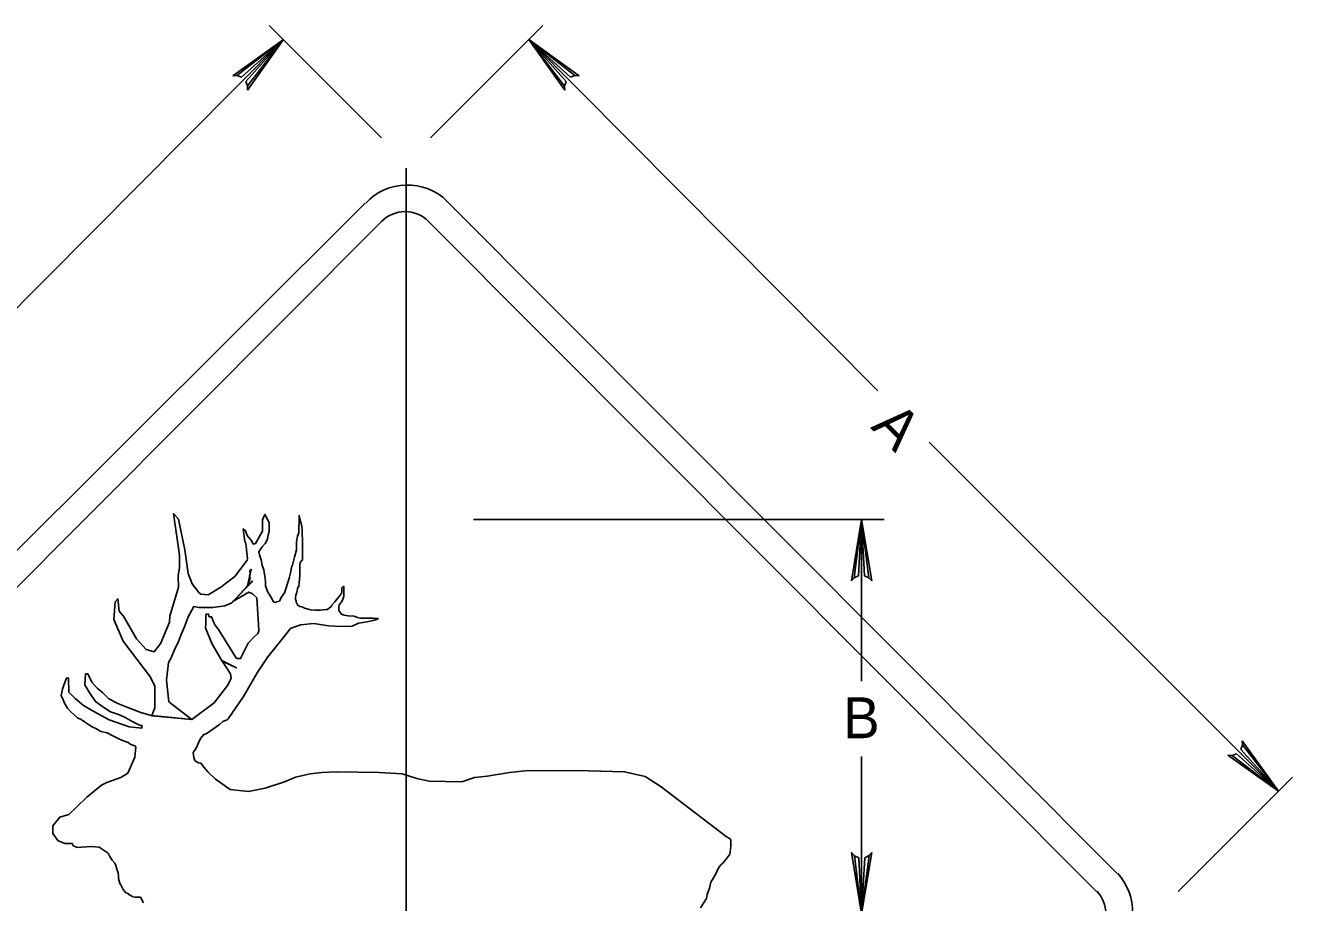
# Model space of a CAD drawing. Extents: x 0.013 to 0.196, y 0.005 to 0.259.
# Drawn here: x 0.0857 to 0.1633, y 0.1514 to 0.2051 of the extents above; entities that cross this region are included whole.
import ezdxf

# ---------------------------------------------------------------- set-up
doc = ezdxf.new("R2010")
doc.units = 0
doc.layers.add('11', color=7, linetype='Continuous')
doc.layers.add('3', color=7, linetype='Continuous')

# ---------------------------------------------------------------- blocks, each defined once
blk = doc.blocks.new('RARROW')
at = {"layer": '3'}
for p, q in [((-2.156, 0.28500000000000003), (-2.2665, 0.384625)), ((-2.2665, 0.384625), (0, 0)), ((0, 0), (-2.2665, -0.379125)), ((-2.156, 0.28500000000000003), (-2.075625, 0.12075)), ((0, 0), (-2.156, 0.28500000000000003)), ((-2.14975, -0.2705), (0, 0)), ((-2.075625, 0.12075), (0, 0)), ((0, 0), (-2.074, -0.108)), ((-2.2665, -0.379125), (-2.14975, -0.2705)), ((-2.074, -0.108), (-2.14975, -0.2705))]:
    blk.add_line(p, q, dxfattribs=at)

msp = doc.modelspace()

# ---------------------------------------------------------------- linework, layer by layer
at = {"layer": '11'}
for p, q in [((0.0655, 0.153375), (0.1065, 0.19425)), ((0.1115, 0.194375), (0.1525, 0.15325))]:
    msp.add_line(p, q, dxfattribs=at)
for centre, radius, start, end in [((0.10907575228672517, 0.19186675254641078), 0.003488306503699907, 45.97564444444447, 136.90506388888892), ((0.1499707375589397, 0.1508906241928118), 0.0034797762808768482, 313.70333055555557, 42.689416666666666)]:
    msp.add_arc(centre, radius, start, end, dxfattribs=at)
at = {"layer": '3'}
for p, q in [((0.1075, 0.19825), (0.100625, 0.205125)), ((0.1105, 0.19825), (0.11737500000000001, 0.205125)), ((0.080125, 0.18275), (0.1015, 0.20425000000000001)), ((0.137875, 0.18275), (0.1165, 0.20425000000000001)), ((0.109, 0.196375), (0.109, 0.104875)), ((0.066625, 0.152125), (0.1075, 0.193125)), ((0.110375, 0.193125), (0.15125, 0.152125)), ((0.14100000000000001, 0.179625), (0.162375, 0.15825)), ((0.113125, 0.174875), (0.13825, 0.174875)), ((0.136875, 0.174875), (0.136875, 0.165)), ((0.0995928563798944, 0.1703369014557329), (0.09987321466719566, 0.17009004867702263)), ((0.08975982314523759, 0.1649307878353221), (0.08957767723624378, 0.165318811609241)), ((0.09010134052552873, 0.16456559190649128), (0.08975982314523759, 0.1649307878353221)), ((0.09044285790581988, 0.16426887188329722), (0.09010134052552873, 0.16456559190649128)), ((0.09080714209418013, 0.1639036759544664), (0.09044285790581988, 0.16426887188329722)), ((0.09135357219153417, 0.16362977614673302), (0.09080714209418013, 0.1639036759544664)), ((0.0919683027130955, 0.16337870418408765), (0.09135357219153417, 0.16362977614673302)), ((0.09276517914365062, 0.16308198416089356), (0.0919683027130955, 0.16337870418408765)), ((0.093470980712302, 0.16287656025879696), (0.09276517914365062, 0.16308198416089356)), ((0.09587879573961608, 0.16264294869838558), (0.093470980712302, 0.16287656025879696)), ((0.136875, 0.160375), (0.136875, 0.15075)), ((0.15625, 0.152125), (0.16325, 0.15912500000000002))]:
    msp.add_line(p, q, dxfattribs=at)
for points in [[(0.10062946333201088, 0.1746769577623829), (0.10051819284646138, 0.17489971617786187), (0.1003608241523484, 0.17520104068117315), (0.10021919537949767, 0.17487374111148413), (0.10020870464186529, 0.17416199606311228), (0.09978906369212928, 0.1734086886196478), (0.09963694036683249, 0.17338271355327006), (0.09955301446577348, 0.17354895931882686), (0.09927499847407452, 0.17389704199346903), (0.09917533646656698, 0.17418277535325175), (0.09903370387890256, 0.17430746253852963), (0.09912812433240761, 0.17353857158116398), (0.09920156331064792, 0.17342427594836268), (0.09922254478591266, 0.1732476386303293), (0.09929497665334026, 0.17248803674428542), (0.09927790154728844, 0.17240018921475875), (0.098529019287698, 0.17140554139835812), (0.09766964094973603, 0.170742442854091), (0.09689620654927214, 0.1702758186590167), (0.09644196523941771, 0.1703126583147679), (0.09630692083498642, 0.17042317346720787), (0.09590178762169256, 0.1709511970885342), (0.09565625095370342, 0.17158973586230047), (0.09545982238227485, 0.17302487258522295), (0.09507924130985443, 0.17490365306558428), (0.09477232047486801, 0.1752474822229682), (0.095128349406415, 0.1727056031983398), (0.095128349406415, 0.17195654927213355), (0.09504240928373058, 0.17144080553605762), (0.09507924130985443, 0.17074086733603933), (0.09455133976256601, 0.1689726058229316), (0.09452678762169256, 0.16859666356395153), (0.0942566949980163, 0.16797040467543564), (0.09398660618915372, 0.16731958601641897), (0.09358147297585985, 0.16677928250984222), (0.09309040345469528, 0.16693891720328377), (0.09250111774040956, 0.16758973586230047), (0.09170312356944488, 0.16897732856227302), (0.09144531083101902, 0.1692843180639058), (0.0913593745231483, 0.1700333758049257), (0.09118749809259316, 0.1698369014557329), (0.09111383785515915, 0.1687685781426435), (0.09167857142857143, 0.16743010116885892), (0.09336049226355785, 0.16524433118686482), (0.09363058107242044, 0.16467947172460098), (0.09363058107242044, 0.16335327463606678), (0.09344642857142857, 0.16288665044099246), (0.09588950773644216, 0.16264105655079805), (0.09447767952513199, 0.16373394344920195), (0.09434263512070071, 0.16506013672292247), (0.09446540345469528, 0.16612846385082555), (0.09460044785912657, 0.16637405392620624), (0.09482142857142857, 0.166914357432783), (0.09506696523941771, 0.16741782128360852), (0.09521428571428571, 0.1677984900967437), (0.09543526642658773, 0.16831423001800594), (0.09565625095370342, 0.16892506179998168), (0.09601227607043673, 0.1695513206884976), (0.09631919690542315, 0.16950220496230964), (0.09717857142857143, 0.16948992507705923), (0.09791517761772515, 0.1696004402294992), (0.09833259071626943, 0.16978463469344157), (0.09930245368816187, 0.17082840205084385), (0.09951026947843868, 0.17184225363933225), (0.0994378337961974, 0.17172323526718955), (0.09945100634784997, 0.17155793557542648), (0.0994246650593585, 0.17141908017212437), (0.09945100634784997, 0.1712868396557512), (0.09930245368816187, 0.170803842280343), (0.09927790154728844, 0.17077928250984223), (0.09957611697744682, 0.17112814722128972), (0.0995753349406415, 0.17107745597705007), (0.0995753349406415, 0.17107745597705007), (0.0983939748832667, 0.169858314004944), (0.09937611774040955, 0.17044773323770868), (0.0995928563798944, 0.1703369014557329)], [(0.10518303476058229, 0.17072827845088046), (0.10518303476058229, 0.1707739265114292), (0.1051602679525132, 0.17079675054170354), (0.10506919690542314, 0.1707054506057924), (0.10506919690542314, 0.17056850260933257), (0.10506919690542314, 0.17047720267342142), (0.10504643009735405, 0.17036308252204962), (0.10493258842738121, 0.17020330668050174), (0.10477321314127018, 0.17002071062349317), (0.10463660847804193, 0.16983811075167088), (0.10445446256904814, 0.16963268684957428), (0.10440892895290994, 0.1695642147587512), (0.10418124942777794, 0.16938161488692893), (0.10411294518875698, 0.16938161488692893), (0.10374866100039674, 0.1693359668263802), (0.10374866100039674, 0.1693359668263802), (0.10352098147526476, 0.1693359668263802), (0.1034526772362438, 0.1693359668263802), (0.1031566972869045, 0.16935879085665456), (0.10299732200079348, 0.169404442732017), (0.10279240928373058, 0.1694500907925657), (0.1027241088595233, 0.16949573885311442), (0.10261026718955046, 0.16954139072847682), (0.1024964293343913, 0.1695642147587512), (0.10238258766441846, 0.16963268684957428), (0.10231428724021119, 0.16976963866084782), (0.10226874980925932, 0.1698152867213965), (0.10226874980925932, 0.16990658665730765), (0.10222321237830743, 0.1699978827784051), (0.10222321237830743, 0.17008918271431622), (0.10224598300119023, 0.17024895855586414), (0.10231428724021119, 0.17040873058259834), (0.10235982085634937, 0.17065980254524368), (0.10242812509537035, 0.17079675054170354), (0.10245089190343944, 0.17100217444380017), (0.10247366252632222, 0.17123042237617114), (0.1024964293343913, 0.17145867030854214), (0.1024964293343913, 0.1717553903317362), (0.1024964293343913, 0.17202928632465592), (0.1025191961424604, 0.1722575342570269), (0.10265580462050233, 0.17241731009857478), (0.10265580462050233, 0.17259990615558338), (0.10265580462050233, 0.1731248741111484), (0.10265580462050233, 0.17317052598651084), (0.10265580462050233, 0.1733987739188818), (0.10265580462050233, 0.1736726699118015), (0.10263303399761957, 0.1739465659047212), (0.10263303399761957, 0.17422046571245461), (0.10261026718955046, 0.1744487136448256), (0.10256473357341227, 0.17472260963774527), (0.1024964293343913, 0.17492803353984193), (0.10245089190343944, 0.17513345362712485), (0.10245089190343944, 0.17513345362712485), (0.10245089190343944, 0.17513345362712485), (0.10245089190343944, 0.17497368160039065), (0.10245089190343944, 0.1747910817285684), (0.10245089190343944, 0.1746769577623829), (0.10242812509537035, 0.1744487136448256), (0.10242812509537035, 0.17435741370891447), (0.10242812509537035, 0.17406068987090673), (0.10235982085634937, 0.17385526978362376), (0.10229151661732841, 0.17353572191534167), (0.10229151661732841, 0.17330747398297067), (0.10229151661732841, 0.17303357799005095), (0.10222321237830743, 0.17280533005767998), (0.10217767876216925, 0.172577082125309), (0.1020866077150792, 0.1722575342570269), (0.10204107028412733, 0.17209776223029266), (0.10199553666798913, 0.17196081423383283), (0.10194999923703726, 0.1717097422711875), (0.10183616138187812, 0.17129889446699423), (0.10156294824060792, 0.17038590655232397), (0.10154017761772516, 0.17038590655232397), (0.10144910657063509, 0.17024895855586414), (0.10135803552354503, 0.1701120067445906), (0.10128973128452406, 0.16997505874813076), (0.10124419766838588, 0.1698837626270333), (0.10106205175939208, 0.16983811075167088), (0.1010165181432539, 0.1698152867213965), (0.10087990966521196, 0.16983811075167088), (0.10072053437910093, 0.170157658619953), (0.10051562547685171, 0.17047720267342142), (0.10040178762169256, 0.1708195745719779), (0.10040178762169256, 0.17104782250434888), (0.10037901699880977, 0.17129889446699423), (0.10033348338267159, 0.1715271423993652), (0.10028794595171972, 0.17180103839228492), (0.10019687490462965, 0.17207493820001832), (0.1001285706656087, 0.17241731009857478), (0.10008303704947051, 0.1725314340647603), (0.10003749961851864, 0.17271403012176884), (0.09999196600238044, 0.17289662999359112), (0.10006026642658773, 0.17303357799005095), (0.10019687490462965, 0.17321617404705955), (0.10037901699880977, 0.17342159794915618), (0.10051562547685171, 0.1736726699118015), (0.1005611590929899, 0.1739465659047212), (0.10062946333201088, 0.17415198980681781), (0.10062946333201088, 0.17438023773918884), (0.10062946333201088, 0.17454000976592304), (0.10062946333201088, 0.1746769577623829)], [(0.12701339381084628, 0.15112104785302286), (0.12737767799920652, 0.15169166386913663), (0.1274232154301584, 0.151942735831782), (0.12755982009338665, 0.15233075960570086), (0.1276508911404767, 0.1526959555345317), (0.12781026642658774, 0.15294702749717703), (0.12796964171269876, 0.1532437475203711), (0.12808348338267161, 0.15349481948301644), (0.12824285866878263, 0.1537230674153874), (0.12837946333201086, 0.1538600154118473), (0.128561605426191, 0.15408826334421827), (0.12876651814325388, 0.1543393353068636), (0.12881205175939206, 0.15440781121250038), (0.12883482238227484, 0.15454475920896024), (0.12885758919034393, 0.15470453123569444), (0.12888035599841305, 0.15490995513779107), (0.12888035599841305, 0.15509255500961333), (0.12888035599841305, 0.15529797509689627), (0.128720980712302, 0.15541209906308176), (0.12858437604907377, 0.1554805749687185), (0.12460000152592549, 0.15851626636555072), (0.12362098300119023, 0.15915535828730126), (0.12236875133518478, 0.159452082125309), (0.1201602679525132, 0.15949773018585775), (0.11649464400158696, 0.15952055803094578), (0.11533348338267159, 0.15940643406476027), (0.11396741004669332, 0.1591781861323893), (0.11319330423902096, 0.15908688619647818), (0.11241919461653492, 0.15883581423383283), (0.11041562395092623, 0.15888146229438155), (0.10966428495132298, 0.15904123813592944), (0.10875357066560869, 0.15931513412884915), (0.10734196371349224, 0.15940643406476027), (0.104727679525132, 0.159452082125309), (0.10383973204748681, 0.15940643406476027), (0.10313392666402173, 0.15931513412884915), (0.10222321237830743, 0.15910971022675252), (0.10156294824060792, 0.15883581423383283), (0.10037901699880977, 0.1584477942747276), (0.09935446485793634, 0.158242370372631), (0.09823883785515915, 0.15835649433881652), (0.09732812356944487, 0.15899558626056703), (0.09687276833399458, 0.159452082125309), (0.09664508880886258, 0.15970315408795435), (0.09644017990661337, 0.15997705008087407), (0.09628080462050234, 0.1599998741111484), (0.09607589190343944, 0.16013682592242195), (0.09600758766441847, 0.16031942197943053), (0.09596205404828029, 0.16061614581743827), (0.0961441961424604, 0.160890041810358), (0.09630357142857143, 0.1612095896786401), (0.09641740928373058, 0.16148348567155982), (0.09659955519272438, 0.1617117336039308), (0.0968272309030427, 0.16180303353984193), (0.09716874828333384, 0.16205410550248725), (0.09730535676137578, 0.16214540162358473), (0.09760134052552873, 0.16235082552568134), (0.09778348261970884, 0.1625334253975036), (0.09805669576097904, 0.16262472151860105), (0.09810223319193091, 0.16269319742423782), (0.09905848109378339, 0.1640634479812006), (0.09987812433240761, 0.16550140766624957), (0.1005383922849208, 0.1664828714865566), (0.10140357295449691, 0.16753281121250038), (0.10192723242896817, 0.16821755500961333), (0.1025419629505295, 0.1684458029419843), (0.10333883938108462, 0.16851427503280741), (0.10427232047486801, 0.16837732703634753), (0.10500089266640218, 0.16833167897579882), (0.10570669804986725, 0.1683545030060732), (0.10609374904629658, 0.16853709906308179), (0.10661741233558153, 0.16862839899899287), (0.10705000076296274, 0.16871969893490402), (0.10718660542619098, 0.16876534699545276), (0.10725490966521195, 0.16881099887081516), (0.10730044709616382, 0.16881099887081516), (0.10727768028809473, 0.16883382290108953), (0.10698169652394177, 0.16885664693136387), (0.10652633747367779, 0.16885664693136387), (0.10620759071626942, 0.16885664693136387), (0.10602544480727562, 0.16887947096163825), (0.10582053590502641, 0.16897077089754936), (0.10545625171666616, 0.16899359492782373), (0.10520580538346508, 0.16903924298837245), (0.10504643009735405, 0.16908489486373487), (0.10500089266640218, 0.16915336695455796), (0.10490982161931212, 0.16926749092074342), (0.10488705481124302, 0.16931314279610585), (0.10488705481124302, 0.169404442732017), (0.10488705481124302, 0.16954139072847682), (0.10490982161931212, 0.1696555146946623), (0.10500089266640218, 0.16979246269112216), (0.10509196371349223, 0.16990658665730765), (0.10518303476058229, 0.17018048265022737), (0.10518303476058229, 0.17031743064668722), (0.10518303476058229, 0.17045437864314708), (0.10518303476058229, 0.17063697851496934), (0.10518303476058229, 0.17072827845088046)], [(0.09987321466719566, 0.17009004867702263), (0.0999741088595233, 0.16842884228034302), (0.09996540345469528, 0.16845529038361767), (0.09996782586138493, 0.16844745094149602), (0.0999784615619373, 0.1680717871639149), (0.09991752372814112, 0.16789546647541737), (0.09992187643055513, 0.16790428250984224), (0.09969213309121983, 0.16767868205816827), (0.09933002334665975, 0.1673217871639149), (0.09887276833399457, 0.1663687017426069), (0.09862723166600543, 0.1663809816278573), (0.09751004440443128, 0.168149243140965), (0.097301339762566, 0.16844395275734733), (0.09709263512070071, 0.16893513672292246), (0.09695759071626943, 0.16893513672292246), (0.09689620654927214, 0.16910705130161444), (0.09674888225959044, 0.16908249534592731), (0.09674888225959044, 0.1688369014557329), (0.09673660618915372, 0.16850535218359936), (0.096724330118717, 0.16824748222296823), (0.09711718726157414, 0.1673019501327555), (0.09774330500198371, 0.16622134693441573), (0.09861501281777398, 0.16580651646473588), (0.09773102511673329, 0.16625818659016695), (0.09825892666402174, 0.16544773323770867), (0.09829575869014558, 0.16515302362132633), (0.09807946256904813, 0.16472292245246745), (0.09725089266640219, 0.163664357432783), (0.09587879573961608, 0.16264294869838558)], [(0.08957767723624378, 0.165318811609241), (0.0895321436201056, 0.1654329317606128), (0.08937276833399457, 0.1654329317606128), (0.08935000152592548, 0.1647710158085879), (0.08960044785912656, 0.16431451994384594), (0.0899874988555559, 0.16374390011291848), (0.09044285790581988, 0.16342435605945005), (0.09092098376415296, 0.16310480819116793), (0.09146741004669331, 0.16292221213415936), (0.09185446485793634, 0.16273961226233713), (0.09228705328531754, 0.16251136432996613), (0.09251473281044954, 0.16237441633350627), (0.09274241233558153, 0.16228311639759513), (0.09283348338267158, 0.16228311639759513), (0.09283348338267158, 0.16212334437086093), (0.09205937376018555, 0.1621918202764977), (0.09082990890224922, 0.16262548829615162), (0.08989642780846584, 0.1631276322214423), (0.08925892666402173, 0.16349282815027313), (0.08875803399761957, 0.16392649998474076), (0.08837098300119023, 0.16431451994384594), (0.08834821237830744, 0.16518185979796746), (0.0882116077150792, 0.16518185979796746), (0.08807499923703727, 0.16481666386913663), (0.08798392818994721, 0.16449711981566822), (0.08789285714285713, 0.16410909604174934), (0.0880066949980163, 0.163858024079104), (0.08809776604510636, 0.16365260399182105), (0.08827991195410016, 0.16333305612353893), (0.08846205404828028, 0.1631276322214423), (0.08868973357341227, 0.16292221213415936), (0.08889464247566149, 0.16273961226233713), (0.08912232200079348, 0.162648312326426), (0.08932723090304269, 0.16251136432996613), (0.08962321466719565, 0.1623059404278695), (0.08978258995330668, 0.1621918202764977), (0.09005580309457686, 0.1620776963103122), (0.09032901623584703, 0.1619179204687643), (0.09071607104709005, 0.16182662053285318), (0.09105758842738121, 0.16164402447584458), (0.09137633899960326, 0.16148425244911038), (0.09164955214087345, 0.1613701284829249), (0.09199107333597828, 0.16123318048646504), (0.09215044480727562, 0.16111905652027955), (0.0924008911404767, 0.16102775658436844), (0.09246919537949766, 0.16095928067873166), (0.0924008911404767, 0.1603430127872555), (0.09212767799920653, 0.1597267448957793), (0.0919683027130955, 0.15936154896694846), (0.09153571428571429, 0.15908765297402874), (0.09069330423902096, 0.158790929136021), (0.09035178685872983, 0.1586311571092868), (0.08946383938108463, 0.1579007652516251), (0.08882633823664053, 0.15727101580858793), (0.08837098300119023, 0.1568373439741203), (0.08780178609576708, 0.1566775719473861), (0.08739196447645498, 0.156129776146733), (0.08739196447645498, 0.1556732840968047), (0.08768794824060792, 0.15523961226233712), (0.08796116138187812, 0.1551254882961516), (0.08814330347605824, 0.15505701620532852), (0.08857589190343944, 0.15505701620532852), (0.08859866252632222, 0.15494289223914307), (0.08887187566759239, 0.1548059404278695), (0.08973705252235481, 0.15487441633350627), (0.09021517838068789, 0.15482876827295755), (0.09076160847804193, 0.1544635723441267), (0.09087544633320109, 0.1542581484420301), (0.09101205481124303, 0.15402990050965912), (0.09117143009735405, 0.15384730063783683), (0.09123973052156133, 0.153710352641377), (0.09130803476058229, 0.15348210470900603), (0.09137633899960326, 0.15325386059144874), (0.09139910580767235, 0.15307126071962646), (0.09139910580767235, 0.15291148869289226), (0.0914901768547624, 0.1526147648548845), (0.09153571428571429, 0.15252346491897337), (0.09158125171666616, 0.15245499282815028), (0.0916950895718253, 0.15224956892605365), (0.09176339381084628, 0.15213544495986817), (0.09185446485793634, 0.15204414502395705), (0.09201384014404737, 0.15197567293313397), (0.09203660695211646, 0.15193002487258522), (0.09226428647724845, 0.1518159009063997), (0.09228705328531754, 0.15179307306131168), (0.09242366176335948, 0.15177024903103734), (0.09249196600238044, 0.15177024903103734), (0.0925830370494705, 0.15177024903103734), (0.09267410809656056, 0.15177024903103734), (0.09271964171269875, 0.15177024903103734), (0.09274241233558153, 0.15177024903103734), (0.09292455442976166, 0.15142787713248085)]]:
    msp.add_lwpolyline(points, dxfattribs=at)
for centre, radius, start, end in [((0.10893750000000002, 0.19171063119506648), 0.0020166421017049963, 44.535288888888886, 135.46470833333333), ((0.14984518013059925, 0.15076449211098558), 0.0019759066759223, 315.3142833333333, 44.30036944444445)]:
    msp.add_arc(centre, radius, start, end, dxfattribs=at)

# ---------------------------------------------------------------- block references
for p, xscale, yscale, rotation in [((0.1015, 0.20425000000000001), 0.001654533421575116, 0.001636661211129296, 45), ((0.1165, 0.20425000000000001), 0.001654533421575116, 0.001636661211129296, 135), ((0.136875, 0.174875), 0.0016545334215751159, 0.0016366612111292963, 90), ((0.162375, 0.15825), 0.0016545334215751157, 0.001636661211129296, -45), ((0.136875, 0.15075), 0.0016545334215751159, 0.0016366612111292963, -90)]:
    msp.add_blockref('RARROW', p, dxfattribs=dict(at, xscale=xscale, yscale=yscale, rotation=rotation))

# ---------------------------------------------------------------- texts
msp.add_text('A', height=0.0024997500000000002, rotation=315, dxfattribs=at).set_placement((0.137375, 0.1805))
msp.add_text('B', height=0.0024997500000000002, dxfattribs=at).set_placement((0.13575, 0.1615))

doc.saveas('drawing.dxf')
